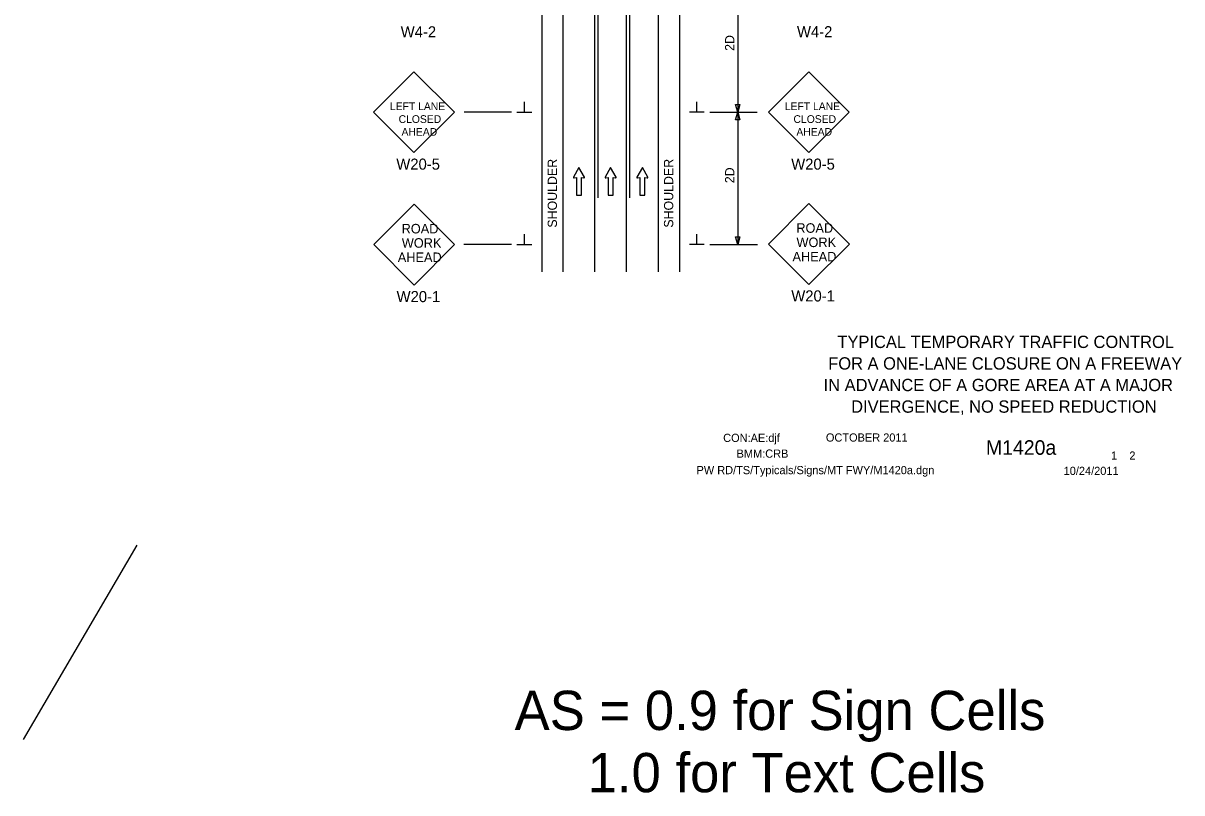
# Model space of a CAD drawing. Extents: x 16562 to 18475, y 6979 to 8243.
# Drawn here: x 16562 to 17437, y 6979 to 7561 of the extents above; entities that cross this region are included whole.
import ezdxf

# ---------------------------------------------------------------- set-up
doc = ezdxf.new("R2010")
doc.units = 0
for name, color, linetype in [('ALI_LEGAL_EX', 7, 'Continuous'), ('BORDER', 7, 'Continuous'), ('BORDER_SIGNAL_WO', 7, 'Continuous'), ('MT_SCRATCH_LEVEL_E', 7, 'Continuous'), ('PAVT_EDGE_EX', 7, 'Continuous'), ('TRAFFIC_SIGNS_PR', 7, 'Continuous'), ('TYPICAL_TEXT_DIMEN_PR', 7, 'Continuous')]:
    doc.layers.add(name, color=color, linetype=linetype)

msp = doc.modelspace()

# ---------------------------------------------------------------- linework, layer by layer
at = {"layer": 'ALI_LEGAL_EX'}
for p, q in [((16995.95, 8243.16), (16995.95, 7428.9)), ((17019.95, 8243.16), (17019.95, 7428.9)), ((16993.65, 7372.88), (16993.65, 7799.18)), ((17017.65, 7372.88), (17017.65, 7799.18))]:
    msp.add_line(p, q, dxfattribs=at)
for points in [[(16993.65, 7498.83), (16993.65, 7523.83)], [(17017.65, 7498.83), (17017.65, 7523.83)], [(16993.65, 7398.83), (16993.65, 7423.83)], [(17017.65, 7398.83), (17017.65, 7423.83)]]:
    msp.add_lwpolyline(points, dxfattribs=at)
at = {"layer": 'MT_SCRATCH_LEVEL_E'}
for p, q in [((16981.67, 7451.73), (16977.55, 7444.49)), ((16985.81, 7444.49), (16981.67, 7451.73)), ((17005.57, 7451.73), (17001.46, 7444.49)), ((17009.72, 7444.49), (17005.57, 7451.73)), ((17029.62, 7451.73), (17025.51, 7444.49)), ((17033.77, 7444.49), (17029.62, 7451.73)), ((16978.04, 7443.81), (16979.81, 7444.12)), ((16979.81, 7444.12), (16979.81, 7430.86)), ((16983.56, 7430.86), (16983.56, 7444.12)), ((16983.56, 7444.12), (16985.33, 7443.81)), ((17001.94, 7443.81), (17003.72, 7444.12)), ((17003.72, 7444.12), (17003.72, 7430.86)), ((17007.46, 7430.86), (17007.46, 7444.12)), ((17007.46, 7444.12), (17009.24, 7443.81)), ((17025.99, 7443.81), (17027.77, 7444.12)), ((17027.77, 7444.12), (17027.77, 7430.86)), ((17031.51, 7430.86), (17031.51, 7444.12)), ((17031.51, 7444.12), (17033.29, 7443.81)), ((16979.81, 7430.86), (16983.56, 7430.86)), ((17003.72, 7430.86), (17007.46, 7430.86)), ((17027.77, 7430.86), (17031.51, 7430.86))]:
    msp.add_line(p, q, dxfattribs=at)
for centre, start, end in [((16977.96, 7444.27), 150.42484, 279.96381), ((16985.4, 7444.27), 260.03619, 29.77312), ((17001.87, 7444.27), 150.42484, 279.96381), ((17009.31, 7444.27), 260.03619, 29.77312), ((17025.92, 7444.27), 150.42484, 279.96381), ((17033.36, 7444.27), 260.03619, 29.77312)]:
    msp.add_arc(centre, 0.463, start, end, dxfattribs=at)
at = {"layer": 'PAVT_EDGE_EX'}
for p, q in [((16953.65, 7799.18), (16953.65, 7372.88)), ((16969.65, 7799.18), (16969.65, 7372.88)), ((17041.65, 7799.18), (17041.65, 7372.88)), ((17057.65, 7799.18), (17057.65, 7372.88))]:
    msp.add_line(p, q, dxfattribs=at)
at = {"layer": 'TRAFFIC_SIGNS_PR'}
for p, q in [((16857.04, 7524.07), (16826.49, 7493.52)), ((16887.59, 7493.52), (16857.04, 7524.07)), ((17155.4, 7524.07), (17124.85, 7493.52)), ((17185.94, 7493.52), (17155.4, 7524.07)), ((16826.49, 7493.52), (16857.04, 7462.97)), ((16857.04, 7462.97), (16887.59, 7493.52)), ((17124.85, 7493.52), (17155.4, 7462.97)), ((17155.4, 7462.97), (17185.94, 7493.52)), ((16857.26, 7423.99), (16826.71, 7393.44)), ((16887.81, 7393.44), (16857.26, 7423.99)), ((17155.47, 7424.47), (17124.93, 7393.92)), ((17186.02, 7393.92), (17155.47, 7424.47)), ((16826.71, 7393.44), (16857.26, 7362.89)), ((16857.26, 7362.89), (16887.81, 7393.44)), ((17124.93, 7393.92), (17155.47, 7363.38)), ((17155.47, 7363.38), (17186.02, 7393.92))]:
    msp.add_line(p, q, dxfattribs=at)
at = {"layer": 'TYPICAL_TEXT_DIMEN_PR'}
for p, q in [((17101.65, 7593.52), (17101.65, 7493.52)), ((16940.52, 7493.52), (16940.52, 7501.31)), ((17070.77, 7493.52), (17070.77, 7501.31)), ((17101.65, 7493.52), (17100.08, 7499.38)), ((17100.08, 7499.38), (17101.65, 7499.38)), ((17101.65, 7499.38), (17103.22, 7499.38)), ((17103.22, 7499.38), (17101.65, 7493.52)), ((16930.65, 7493.52), (16894.91, 7493.52)), ((16934.9, 7493.52), (16946.15, 7493.52)), ((17076.4, 7493.52), (17065.15, 7493.52)), ((17080.65, 7493.52), (17116.31, 7493.52)), ((17100.08, 7487.66), (17101.65, 7493.52)), ((17101.65, 7487.66), (17100.08, 7487.66)), ((17101.65, 7493.52), (17101.65, 7393.52)), ((17101.65, 7493.52), (17103.22, 7487.66)), ((17103.22, 7487.66), (17101.65, 7487.66)), ((16940.52, 7393.52), (16940.52, 7401.31)), ((17070.77, 7393.52), (17070.77, 7401.31)), ((17101.65, 7393.52), (17100.08, 7399.38)), ((17100.08, 7399.38), (17101.65, 7399.38)), ((17101.65, 7399.38), (17103.22, 7399.38)), ((17103.22, 7399.38), (17101.65, 7393.52)), ((16930.65, 7393.52), (16894.65, 7393.52)), ((16934.9, 7393.52), (16946.15, 7393.52)), ((17076.4, 7393.52), (17065.15, 7393.52)), ((17080.65, 7393.52), (17116.65, 7393.52)), ((16647.75, 7166.25), (16561.8, 7019.35))]:
    msp.add_line(p, q, dxfattribs=at)

# ---------------------------------------------------------------- texts
at = {"layer": 'BORDER'}
for s, p in [('TYPICAL TEMPORARY TRAFFIC CONTROL', (17177.02, 7315.33)), ('TYPICAL TEMPORARY TRAFFIC CONTROL', (17177.02, 7315.33)), ('FOR A ONE-LANE CLOSURE ON A FREEWAY', (17170.07, 7299.03)), ('FOR A ONE-LANE CLOSURE ON A FREEWAY', (17170.07, 7299.03)), ('IN ADVANCE OF A GORE AREA AT A MAJOR', (17166.57, 7282.73)), ('IN ADVANCE OF A GORE AREA AT A MAJOR', (17166.57, 7282.73)), ('DIVERGENCE, NO SPEED REDUCTION', (17187.38, 7266.43)), ('DIVERGENCE, NO SPEED REDUCTION', (17187.38, 7266.43))]:
    msp.add_text(s, height=9.3, dxfattribs=at).set_placement(p)
at = {"layer": 'BORDER_SIGNAL_WO'}
for s, height, p in [('CON:AE:djf  ', 6.2, (17090.69, 7244.31)), ('    OCTOBER 2011    ', 6.2, (17159.08, 7244.59)), ('    M1420a   ', 11, (17272.86, 7234.63)), ('BMM:CRB   ', 6.2, (17100.81, 7232.42)), (' 1    2 ', 6.2, (17381.45, 7230.95)), ('PW RD/TS/Typicals/Signs/MT FWY/M1420a.dgn      ', 6.2, (17070.55, 7219.96)), ('10/24/2011    ', 6.2, (17347.93, 7219.38)), ('AS = 0.9 for Sign Cells', 29.7271, (16933.12, 7026.59)), ('     1.0 for Text Cells', 29.7271, (16933.12, 6979.58))]:
    msp.add_text(s, height=height, dxfattribs=at).set_placement(p)
at = {"layer": 'TRAFFIC_SIGNS_PR'}
for s, height, p in [('W4-2', 8.37, (16847.05, 7550.09)), ('W4-2', 8.37, (17146.44, 7550.19)), ('LEFT LANE', 5.85, (16838.91, 7495.09)), ('LEFT LANE', 5.85, (17137.26, 7495.09)), ('CLOSED', 5.85, (16845.47, 7485.41)), ('CLOSED', 5.85, (17143.82, 7485.41)), ('AHEAD', 5.85, (16847.66, 7475.74)), ('AHEAD', 5.85, (17146.01, 7475.74)), ('W20-5', 8.37, (16843.74, 7450.1)), ('W20-5', 8.37, (17142.09, 7450.1)), ('ROAD', 7.2, (16847.74, 7401.92)), ('ROAD', 7.2, (17145.96, 7402.4)), ('WORK', 7.2, (16847.87, 7391.12)), ('WORK', 7.2, (17146.08, 7391.6)), ('AHEAD', 7.2, (16844.84, 7380.32)), ('AHEAD', 7.2, (17143.05, 7380.8)), ('W20-1', 8.37, (16843.95, 7350.02)), ('W20-1', 8.37, (17142.16, 7350.51))]:
    msp.add_text(s, height=height, dxfattribs=at).set_placement(p)
at = {"layer": 'TYPICAL_TEXT_DIMEN_PR'}
for s, p in [('2D', (17099.09, 7539.88)), ('SHOULDER', (16965.09, 7406.28)), ('SHOULDER', (17052.95, 7406.28)), ('2D', (17099.09, 7439.88))]:
    msp.add_text(s, height=7, rotation=90, dxfattribs=at).set_placement(p)

doc.saveas('drawing.dxf')
